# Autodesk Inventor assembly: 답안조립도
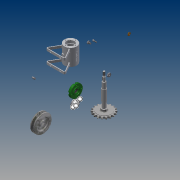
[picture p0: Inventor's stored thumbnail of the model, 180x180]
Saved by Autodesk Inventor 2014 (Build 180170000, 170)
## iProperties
Created: 2016-03
Part Number: 답안조립도
Document SubType Name: Assembly
Designer: 406-12
Author: 406-12
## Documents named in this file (16)
- C:\Users\406-12\Desktop\460307V1007\답안조립도.iam
- C:\Users\406-12\Desktop\460307V1007\V벨트풀리.ipt
- C:\Users\406-12\Desktop\460307V1007\너트 M 8.ipt
- C:\Users\406-12\Desktop\460307V1007\니플 M 6 x 0.75.ipt
- C:\Users\406-12\Desktop\460307V1007\베어링 15 x 32 x 9.ipt
- C:\Users\406-12\Desktop\460307V1007\본체.ipt
- C:\Users\406-12\Desktop\460307V1007\볼트 M 6 x 8.ipt
- C:\Users\406-12\Desktop\460307V1007\볼트 M4 x 12.ipt
- C:\Users\406-12\Desktop\460307V1007\스프로킷.ipt
- C:\Users\406-12\Desktop\460307V1007\스프링와셔 8.ipt
- C:\Users\406-12\Desktop\460307V1007\오일 실 15 25 7.ipt
- C:\Users\406-12\Desktop\460307V1007\와셔 6x11.5.ipt
- C:\Users\406-12\Desktop\460307V1007\와셔 8x17.ipt
- C:\Users\406-12\Desktop\460307V1007\축.ipt
- C:\Users\406-12\Desktop\460307V1007\커버.ipt
- C:\Users\406-12\Desktop\460307V1007\키 3 x 3 x 12.ipt
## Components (3 placed, 3 different names)
1. V벨트풀리:1
2. KS B 2023 6002 - 15 x 32 x 9:1
3. ISO 4762 M4 x 12:1
